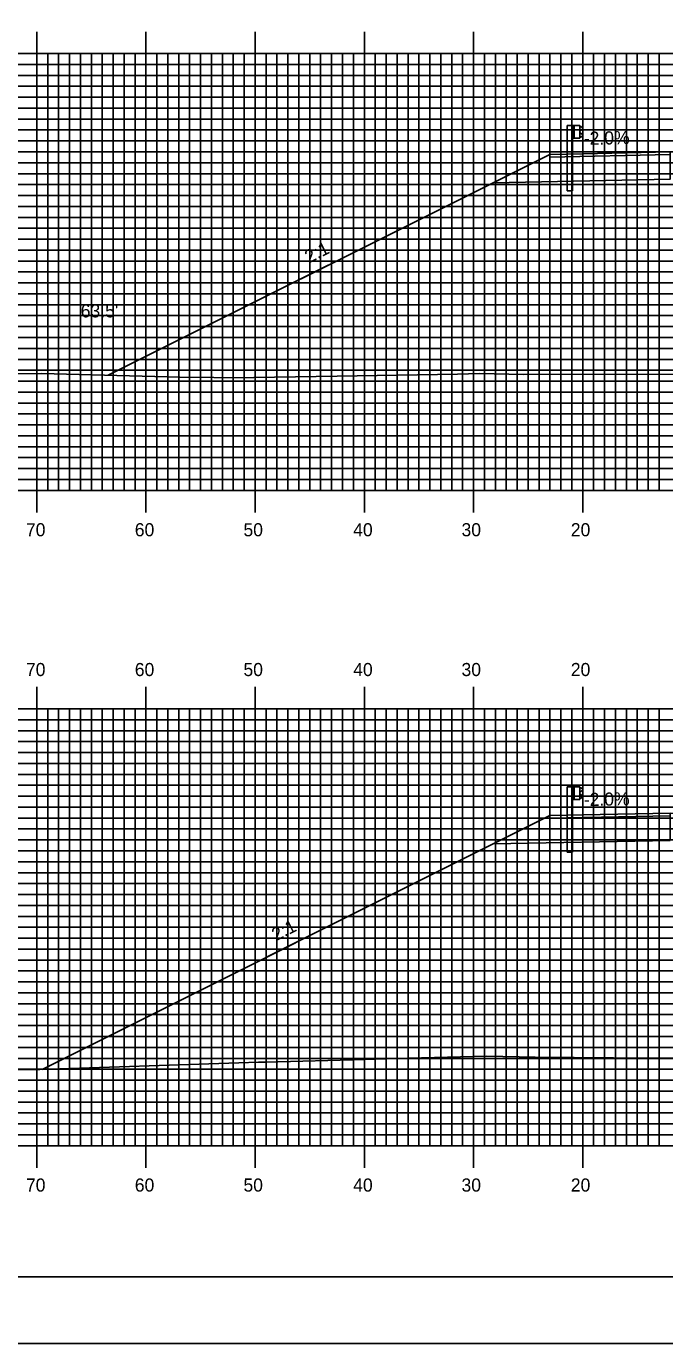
# Model space of a CAD drawing. Extents: x 1811374 to 1811717, y 442591 to 442811.
# Drawn here: x 1811468.4 to 1811526.9, y 442590.5 to 442711.2 of the extents above; entities that cross this region are included whole.
import ezdxf

# ---------------------------------------------------------------- set-up
doc = ezdxf.new("R2010")
doc.units = 0
for name, color, linetype in [('ANNOTATION', 7, 'Continuous'), ('BORDER', 7, 'Continuous'), ('D_Guardrail_Beam_Lt', 7, 'Continuous'), ('D_Roadway_Centerline', 7, 'Continuous'), ('D_Roadway_Edge_Shoulder', 7, 'Continuous'), ('D_Roadway_SlopeLines', 7, 'Continuous'), ('D_Roadway_SubGrade', 7, 'Continuous'), ('D_Text_Standard', 7, 'Continuous'), ('H_V ANNOTATION', 7, 'Continuous'), ('MAJOR', 7, 'Continuous'), ('MINOR', 7, 'Continuous'), ('PLOT BOUNDARY', 7, 'Continuous'), ('S_Roadway_Centerline', 7, 'Continuous')]:
    doc.layers.add(name, color=color, linetype=linetype)

msp = doc.modelspace()

# ---------------------------------------------------------------- linework, layer by layer
at = {"layer": 'BORDER'}
msp.add_lwpolyline([(1811389.8, 442596.67), (1811709.8, 442596.67), (1811709.8, 442806.67), (1811389.8, 442806.67)], close=True, dxfattribs=at)
at = {"layer": 'D_Guardrail_Beam_Lt'}
for p, q in [((1811517.97, 442702.09), (1811517.97, 442696.09)), ((1811518.44, 442702.09), (1811517.97, 442702.09)), ((1811519.13, 442702.09), (1811518.44, 442702.09)), ((1811518.44, 442702.09), (1811518.44, 442700.92)), ((1811518.51, 442702.09), (1811518.51, 442700.92)), ((1811518.61, 442702.09), (1811518.61, 442700.92)), ((1811519.13, 442700.92), (1811519.13, 442702.09)), ((1811519.13, 442702), (1811519.21, 442701.99)), ((1811519.22, 442701.98), (1811519.37, 442701.88)), ((1811518.44, 442700.92), (1811519.13, 442700.92)), ((1811518.47, 442696.09), (1811518.47, 442700.92)), ((1811519.21, 442701.02), (1811519.13, 442701)), ((1811519.14, 442701.54), (1811519.14, 442701.47)), ((1811519.37, 442701.74), (1811519.17, 442701.6)), ((1811519.17, 442701.4), (1811519.37, 442701.27)), ((1811519.37, 442701.12), (1811519.22, 442701.02)), ((1811518.47, 442696.09), (1811517.97, 442696.09)), ((1811517.97, 442641.54), (1811517.97, 442635.54)), ((1811518.44, 442641.54), (1811517.97, 442641.54)), ((1811519.13, 442641.54), (1811518.44, 442641.54)), ((1811518.44, 442641.54), (1811518.44, 442640.38)), ((1811518.44, 442640.38), (1811519.13, 442640.38)), ((1811518.47, 442635.54), (1811518.47, 442640.38)), ((1811518.51, 442641.54), (1811518.51, 442640.38)), ((1811518.61, 442641.54), (1811518.61, 442640.38)), ((1811519.13, 442640.38), (1811519.13, 442641.54)), ((1811519.13, 442641.46), (1811519.21, 442641.45)), ((1811519.21, 442640.48), (1811519.13, 442640.46)), ((1811519.14, 442641), (1811519.14, 442640.93)), ((1811519.37, 442641.2), (1811519.17, 442641.06)), ((1811519.17, 442640.86), (1811519.37, 442640.73)), ((1811519.22, 442641.44), (1811519.37, 442641.34)), ((1811519.37, 442640.58), (1811519.22, 442640.48)), ((1811518.47, 442635.54), (1811517.97, 442635.54))]:
    msp.add_line(p, q, dxfattribs=at)
for centre, major_axis, start_param, end_param in [((1811519.2, 442701.95), (0.0417, 0), 0.959931, 1.376053), ((1811519.32, 442701.81), (0.0877, 0), 5.323254, 7.243116), ((1811519.22, 442701.54), (-0.0789, 0), 5.323254, 6.283185), ((1811519.22, 442701.47), (-0.0789, 0), 6.283185, 7.243116), ((1811519.2, 442701.06), (0.0417, 0), 4.907132, 5.323254), ((1811519.32, 442701.19), (0.0877, 0), 5.323254, 7.243116), ((1811519.22, 442641), (-0.0789, 0), 5.323254, 6.283185), ((1811519.22, 442640.93), (-0.0789, 0), 6.283185, 7.243116), ((1811519.2, 442641.41), (0.0417, 0), 0.959931, 1.376053), ((1811519.2, 442640.52), (0.0417, 0), 4.907132, 5.323254), ((1811519.32, 442641.27), (0.0877, 0), 5.323254, 7.243116), ((1811519.32, 442640.65), (0.0877, 0), 5.323254, 7.243116)]:
    msp.add_ellipse(centre, major_axis=major_axis, ratio=0.995501, start_param=start_param, end_param=end_param, dxfattribs=at)
at = {"layer": 'D_Roadway_Centerline'}
for points in [[(1811475.94, 442679.21), (1811511.19, 442696.84), (1811516.4, 442699.44), (1811519.4, 442699.5), (1811527.4, 442699.66), (1811539.4, 442699.09), (1811551.4, 442698.51), (1811559.4, 442698.13), (1811562.4, 442697.98), (1811567.93, 442695.22), (1811602.42, 442677.97)], [(1811469.9, 442615.65), (1811511.19, 442636.3), (1811516.4, 442638.9), (1811519.4, 442638.96), (1811527.4, 442639.12), (1811539.4, 442638.54), (1811551.4, 442637.97), (1811559.4, 442637.58), (1811562.4, 442637.44), (1811567.93, 442634.68), (1811605.84, 442615.72)]]:
    msp.add_lwpolyline(points, dxfattribs=at)
at = {"layer": 'D_Roadway_Edge_Shoulder'}
for points in [[(1811527.4, 442699.66), (1811519.4, 442699.5), (1811519.4, 442699.5), (1811516.4, 442699.44), (1811516.4, 442699.19), (1811527.4, 442699.41)], [(1811527.4, 442639.12), (1811519.4, 442638.96), (1811519.4, 442638.96), (1811516.4, 442638.9), (1811516.4, 442638.65), (1811527.4, 442638.87)]]:
    msp.add_lwpolyline(points, close=True, dxfattribs=at)
at = {"layer": 'D_Roadway_SlopeLines'}
for points in [[(1811516.4, 442699.44), (1811475.94, 442679.21)], [(1811516.4, 442638.9), (1811469.9, 442615.65)]]:
    msp.add_lwpolyline(points, dxfattribs=at)
at = {"layer": 'D_Roadway_SubGrade'}
for points in [[(1811527.4, 442699), (1811527.4, 442699.41), (1811516.4, 442699.19), (1811516.4, 442699.44), (1811511.19, 442696.84), (1811527.4, 442697.16)], [(1811527.4, 442638.45), (1811527.4, 442638.87), (1811516.4, 442638.65), (1811516.4, 442638.9), (1811511.19, 442636.3), (1811527.4, 442636.62)]]:
    msp.add_lwpolyline(points, close=True, dxfattribs=at)
at = {"layer": 'MAJOR'}
for p, q in [((1811469.4, 442710.67), (1811469.4, 442708.67)), ((1811479.4, 442710.67), (1811479.4, 442708.67)), ((1811489.4, 442710.67), (1811489.4, 442708.67)), ((1811499.4, 442710.67), (1811499.4, 442708.67)), ((1811509.4, 442710.67), (1811509.4, 442708.67)), ((1811519.4, 442710.67), (1811519.4, 442708.67)), ((1811399.4, 442708.67), (1811679.4, 442708.67)), ((1811399.4, 442708.67), (1811679.4, 442708.67)), ((1811469.4, 442668.67), (1811469.4, 442708.67)), ((1811479.4, 442668.67), (1811479.4, 442708.67)), ((1811489.4, 442668.67), (1811489.4, 442708.67)), ((1811499.4, 442668.67), (1811499.4, 442708.67)), ((1811509.4, 442668.67), (1811509.4, 442708.67)), ((1811519.4, 442668.67), (1811519.4, 442708.67)), ((1811399.4, 442703.67), (1811679.4, 442703.67)), ((1811399.4, 442698.67), (1811679.4, 442698.67)), ((1811399.4, 442693.67), (1811679.4, 442693.67)), ((1811399.4, 442688.67), (1811679.4, 442688.67)), ((1811399.4, 442683.67), (1811679.4, 442683.67)), ((1811399.4, 442678.67), (1811679.4, 442678.67)), ((1811399.4, 442673.67), (1811679.4, 442673.67)), ((1811399.4, 442668.67), (1811679.4, 442668.67)), ((1811399.4, 442668.67), (1811679.4, 442668.67)), ((1811469.4, 442666.66), (1811469.4, 442668.67)), ((1811479.4, 442666.66), (1811479.4, 442668.67)), ((1811489.4, 442666.66), (1811489.4, 442668.67)), ((1811499.4, 442666.66), (1811499.4, 442668.67)), ((1811509.4, 442666.66), (1811509.4, 442668.67)), ((1811519.4, 442666.66), (1811519.4, 442668.67)), ((1811469.4, 442650.67), (1811469.4, 442648.67)), ((1811479.4, 442650.67), (1811479.4, 442648.67)), ((1811489.4, 442650.67), (1811489.4, 442648.67)), ((1811499.4, 442650.67), (1811499.4, 442648.67)), ((1811509.4, 442650.67), (1811509.4, 442648.67)), ((1811519.4, 442650.67), (1811519.4, 442648.67)), ((1811399.4, 442648.67), (1811679.4, 442648.67)), ((1811399.4, 442648.67), (1811679.4, 442648.67)), ((1811469.4, 442608.67), (1811469.4, 442648.67)), ((1811479.4, 442608.67), (1811479.4, 442648.67)), ((1811489.4, 442608.67), (1811489.4, 442648.67)), ((1811499.4, 442608.67), (1811499.4, 442648.67)), ((1811509.4, 442608.67), (1811509.4, 442648.67)), ((1811519.4, 442608.67), (1811519.4, 442648.67)), ((1811399.4, 442643.67), (1811679.4, 442643.67)), ((1811399.4, 442638.67), (1811679.4, 442638.67)), ((1811399.4, 442633.67), (1811679.4, 442633.67)), ((1811399.4, 442628.67), (1811679.4, 442628.67)), ((1811399.4, 442623.67), (1811679.4, 442623.67)), ((1811399.4, 442618.67), (1811679.4, 442618.67)), ((1811399.4, 442613.67), (1811679.4, 442613.67)), ((1811399.4, 442608.67), (1811679.4, 442608.67)), ((1811399.4, 442608.67), (1811679.4, 442608.67)), ((1811469.4, 442606.66), (1811469.4, 442608.67)), ((1811479.4, 442606.66), (1811479.4, 442608.67)), ((1811489.4, 442606.66), (1811489.4, 442608.67)), ((1811499.4, 442606.66), (1811499.4, 442608.67)), ((1811509.4, 442606.66), (1811509.4, 442608.67)), ((1811519.4, 442606.66), (1811519.4, 442608.67))]:
    msp.add_line(p, q, dxfattribs=at)
at = {"layer": 'MINOR'}
for p, q in [((1811470.4, 442668.67), (1811470.4, 442708.67)), ((1811471.4, 442668.67), (1811471.4, 442708.67)), ((1811472.4, 442668.67), (1811472.4, 442708.67)), ((1811473.4, 442668.67), (1811473.4, 442708.67)), ((1811474.4, 442668.67), (1811474.4, 442708.67)), ((1811475.4, 442668.67), (1811475.4, 442708.67)), ((1811476.4, 442668.67), (1811476.4, 442708.67)), ((1811477.4, 442668.67), (1811477.4, 442708.67)), ((1811478.4, 442668.67), (1811478.4, 442708.67)), ((1811480.4, 442668.67), (1811480.4, 442708.67)), ((1811481.4, 442668.67), (1811481.4, 442708.67)), ((1811482.4, 442668.67), (1811482.4, 442708.67)), ((1811483.4, 442668.67), (1811483.4, 442708.67)), ((1811484.4, 442668.67), (1811484.4, 442708.67)), ((1811485.4, 442668.67), (1811485.4, 442708.67)), ((1811486.4, 442668.67), (1811486.4, 442708.67)), ((1811487.4, 442668.67), (1811487.4, 442708.67)), ((1811488.4, 442668.67), (1811488.4, 442708.67)), ((1811490.4, 442668.67), (1811490.4, 442708.67)), ((1811491.4, 442668.67), (1811491.4, 442708.67)), ((1811492.4, 442668.67), (1811492.4, 442708.67)), ((1811493.4, 442668.67), (1811493.4, 442708.67)), ((1811494.4, 442668.67), (1811494.4, 442708.67)), ((1811495.4, 442668.67), (1811495.4, 442708.67)), ((1811496.4, 442668.67), (1811496.4, 442708.67)), ((1811497.4, 442668.67), (1811497.4, 442708.67)), ((1811498.4, 442668.67), (1811498.4, 442708.67)), ((1811500.4, 442668.67), (1811500.4, 442708.67)), ((1811501.4, 442668.67), (1811501.4, 442708.67)), ((1811502.4, 442668.67), (1811502.4, 442708.67)), ((1811503.4, 442668.67), (1811503.4, 442708.67)), ((1811504.4, 442668.67), (1811504.4, 442708.67)), ((1811505.4, 442668.67), (1811505.4, 442708.67)), ((1811506.4, 442668.67), (1811506.4, 442708.67)), ((1811507.4, 442668.67), (1811507.4, 442708.67)), ((1811508.4, 442668.67), (1811508.4, 442708.67)), ((1811510.4, 442668.67), (1811510.4, 442708.67)), ((1811511.4, 442668.67), (1811511.4, 442708.67)), ((1811512.4, 442668.67), (1811512.4, 442708.67)), ((1811513.4, 442668.67), (1811513.4, 442708.67)), ((1811514.4, 442668.67), (1811514.4, 442708.67)), ((1811515.4, 442668.67), (1811515.4, 442708.67)), ((1811516.4, 442668.67), (1811516.4, 442708.67)), ((1811517.4, 442668.67), (1811517.4, 442708.67)), ((1811518.4, 442668.67), (1811518.4, 442708.67)), ((1811520.4, 442668.67), (1811520.4, 442708.67)), ((1811521.4, 442668.67), (1811521.4, 442708.67)), ((1811522.4, 442668.67), (1811522.4, 442708.67)), ((1811523.4, 442668.67), (1811523.4, 442708.67)), ((1811524.4, 442668.67), (1811524.4, 442708.67)), ((1811525.4, 442668.67), (1811525.4, 442708.67)), ((1811526.4, 442668.67), (1811526.4, 442708.67)), ((1811399.4, 442707.67), (1811679.4, 442707.67)), ((1811399.4, 442706.67), (1811679.4, 442706.67)), ((1811399.4, 442705.67), (1811679.4, 442705.67)), ((1811399.4, 442704.67), (1811679.4, 442704.67)), ((1811399.4, 442702.67), (1811679.4, 442702.67)), ((1811399.4, 442701.67), (1811679.4, 442701.67)), ((1811399.4, 442700.67), (1811679.4, 442700.67)), ((1811399.4, 442699.67), (1811679.4, 442699.67)), ((1811399.4, 442697.67), (1811679.4, 442697.67)), ((1811399.4, 442696.67), (1811679.4, 442696.67)), ((1811399.4, 442695.67), (1811679.4, 442695.67)), ((1811399.4, 442694.67), (1811679.4, 442694.67)), ((1811399.4, 442692.67), (1811679.4, 442692.67)), ((1811399.4, 442691.67), (1811679.4, 442691.67)), ((1811399.4, 442690.67), (1811679.4, 442690.67)), ((1811399.4, 442689.67), (1811679.4, 442689.67)), ((1811399.4, 442687.67), (1811679.4, 442687.67)), ((1811399.4, 442686.67), (1811679.4, 442686.67)), ((1811399.4, 442685.67), (1811679.4, 442685.67)), ((1811399.4, 442684.67), (1811679.4, 442684.67)), ((1811399.4, 442682.67), (1811679.4, 442682.67)), ((1811399.4, 442681.67), (1811679.4, 442681.67)), ((1811399.4, 442680.67), (1811679.4, 442680.67)), ((1811399.4, 442679.67), (1811679.4, 442679.67)), ((1811399.4, 442677.67), (1811679.4, 442677.67)), ((1811399.4, 442676.67), (1811679.4, 442676.67)), ((1811399.4, 442675.67), (1811679.4, 442675.67)), ((1811399.4, 442674.67), (1811679.4, 442674.67)), ((1811399.4, 442672.67), (1811679.4, 442672.67)), ((1811399.4, 442671.67), (1811679.4, 442671.67)), ((1811399.4, 442670.67), (1811679.4, 442670.67)), ((1811399.4, 442669.67), (1811679.4, 442669.67)), ((1811399.4, 442647.67), (1811679.4, 442647.67)), ((1811470.4, 442608.67), (1811470.4, 442648.67)), ((1811471.4, 442608.67), (1811471.4, 442648.67)), ((1811472.4, 442608.67), (1811472.4, 442648.67)), ((1811473.4, 442608.67), (1811473.4, 442648.67)), ((1811474.4, 442608.67), (1811474.4, 442648.67)), ((1811475.4, 442608.67), (1811475.4, 442648.67)), ((1811476.4, 442608.67), (1811476.4, 442648.67)), ((1811477.4, 442608.67), (1811477.4, 442648.67)), ((1811478.4, 442608.67), (1811478.4, 442648.67)), ((1811480.4, 442608.67), (1811480.4, 442648.67)), ((1811481.4, 442608.67), (1811481.4, 442648.67)), ((1811482.4, 442608.67), (1811482.4, 442648.67)), ((1811483.4, 442608.67), (1811483.4, 442648.67)), ((1811484.4, 442608.67), (1811484.4, 442648.67)), ((1811485.4, 442608.67), (1811485.4, 442648.67)), ((1811486.4, 442608.67), (1811486.4, 442648.67)), ((1811487.4, 442608.67), (1811487.4, 442648.67)), ((1811488.4, 442608.67), (1811488.4, 442648.67)), ((1811490.4, 442608.67), (1811490.4, 442648.67)), ((1811491.4, 442608.67), (1811491.4, 442648.67)), ((1811492.4, 442608.67), (1811492.4, 442648.67)), ((1811493.4, 442608.67), (1811493.4, 442648.67)), ((1811494.4, 442608.67), (1811494.4, 442648.67)), ((1811495.4, 442608.67), (1811495.4, 442648.67)), ((1811496.4, 442608.67), (1811496.4, 442648.67)), ((1811497.4, 442608.67), (1811497.4, 442648.67)), ((1811498.4, 442608.67), (1811498.4, 442648.67)), ((1811500.4, 442608.67), (1811500.4, 442648.67)), ((1811501.4, 442608.67), (1811501.4, 442648.67)), ((1811502.4, 442608.67), (1811502.4, 442648.67)), ((1811503.4, 442608.67), (1811503.4, 442648.67)), ((1811504.4, 442608.67), (1811504.4, 442648.67)), ((1811505.4, 442608.67), (1811505.4, 442648.67)), ((1811506.4, 442608.67), (1811506.4, 442648.67)), ((1811507.4, 442608.67), (1811507.4, 442648.67)), ((1811508.4, 442608.67), (1811508.4, 442648.67)), ((1811510.4, 442608.67), (1811510.4, 442648.67)), ((1811511.4, 442608.67), (1811511.4, 442648.67)), ((1811512.4, 442608.67), (1811512.4, 442648.67)), ((1811513.4, 442608.67), (1811513.4, 442648.67)), ((1811514.4, 442608.67), (1811514.4, 442648.67)), ((1811515.4, 442608.67), (1811515.4, 442648.67)), ((1811516.4, 442608.67), (1811516.4, 442648.67)), ((1811517.4, 442608.67), (1811517.4, 442648.67)), ((1811518.4, 442608.67), (1811518.4, 442648.67)), ((1811520.4, 442608.67), (1811520.4, 442648.67)), ((1811521.4, 442608.67), (1811521.4, 442648.67)), ((1811522.4, 442608.67), (1811522.4, 442648.67)), ((1811523.4, 442608.67), (1811523.4, 442648.67)), ((1811524.4, 442608.67), (1811524.4, 442648.67)), ((1811525.4, 442608.67), (1811525.4, 442648.67)), ((1811526.4, 442608.67), (1811526.4, 442648.67)), ((1811399.4, 442646.67), (1811679.4, 442646.67)), ((1811399.4, 442645.67), (1811679.4, 442645.67)), ((1811399.4, 442644.67), (1811679.4, 442644.67)), ((1811399.4, 442642.67), (1811679.4, 442642.67)), ((1811399.4, 442641.67), (1811679.4, 442641.67)), ((1811399.4, 442640.67), (1811679.4, 442640.67)), ((1811399.4, 442639.67), (1811679.4, 442639.67)), ((1811399.4, 442637.67), (1811679.4, 442637.67)), ((1811399.4, 442636.67), (1811679.4, 442636.67)), ((1811399.4, 442635.67), (1811679.4, 442635.67)), ((1811399.4, 442634.67), (1811679.4, 442634.67)), ((1811399.4, 442632.67), (1811679.4, 442632.67)), ((1811399.4, 442631.67), (1811679.4, 442631.67)), ((1811399.4, 442630.67), (1811679.4, 442630.67)), ((1811399.4, 442629.67), (1811679.4, 442629.67)), ((1811399.4, 442627.67), (1811679.4, 442627.67)), ((1811399.4, 442626.67), (1811679.4, 442626.67)), ((1811399.4, 442625.67), (1811679.4, 442625.67)), ((1811399.4, 442624.67), (1811679.4, 442624.67)), ((1811399.4, 442622.67), (1811679.4, 442622.67)), ((1811399.4, 442621.67), (1811679.4, 442621.67)), ((1811399.4, 442620.67), (1811679.4, 442620.67)), ((1811399.4, 442619.67), (1811679.4, 442619.67)), ((1811399.4, 442617.67), (1811679.4, 442617.67)), ((1811399.4, 442616.67), (1811679.4, 442616.67)), ((1811399.4, 442615.67), (1811679.4, 442615.67)), ((1811399.4, 442614.67), (1811679.4, 442614.67)), ((1811399.4, 442612.67), (1811679.4, 442612.67)), ((1811399.4, 442611.67), (1811679.4, 442611.67)), ((1811399.4, 442610.67), (1811679.4, 442610.67)), ((1811399.4, 442609.67), (1811679.4, 442609.67))]:
    msp.add_line(p, q, dxfattribs=at)
at = {"layer": 'PLOT BOUNDARY'}
msp.add_lwpolyline([(1811373.62, 442590.55), (1811713.62, 442590.55), (1811713.62, 442810.55), (1811373.62, 442810.55)], close=True, dxfattribs=at)
at = {"layer": 'S_Roadway_Centerline'}
for points in [[(1811451.55, 442679.34), (1811469.83, 442679.36), (1811482.49, 442679.05), (1811485.62, 442679), (1811487.37, 442678.98), (1811496.91, 442679.12), (1811507.94, 442679.32), (1811509.95, 442679.36), (1811513.99, 442679.28), (1811534.49, 442679.3), (1811545.39, 442679.21), (1811546.89, 442679.18), (1811558.7, 442679.05), (1811565.95, 442678.73), (1811570.24, 442678.49), (1811581.07, 442678.29), (1811583.44, 442678.27), (1811584.52, 442678.3), (1811590.01, 442678.19), (1811602.72, 442677.97)], [(1811466.87, 442615.61), (1811469.67, 442615.64), (1811487.91, 442616.26), (1811489.7, 442616.33), (1811489.97, 442616.33), (1811490.34, 442616.33), (1811499.49, 442616.56), (1811502.21, 442616.65), (1811510.63, 442616.87), (1811515.03, 442616.78), (1811522.23, 442616.71), (1811535.32, 442616.69), (1811546.76, 442616.67), (1811554.79, 442616.36), (1811563.75, 442616.37), (1811574.07, 442616.6), (1811581.46, 442616.35), (1811593.48, 442615.24), (1811595.85, 442615.25), (1811605.4, 442615.73)]]:
    msp.add_lwpolyline(points, dxfattribs=at)

# ---------------------------------------------------------------- texts
at = {"layer": 'ANNOTATION'}
for s, rotation, p in [('-2.0%', 1.1458, (1811519.51, 442700.3)), ('2:1', 26.5651, (1811494.32, 442689.44)), ('-2.0%', 1.1458, (1811519.51, 442639.76)), ('2:1', 26.5651, (1811491.3, 442627.38))]:
    msp.add_text(s, height=1.2, rotation=rotation, dxfattribs=at).set_placement(p)
at = {"layer": 'D_Text_Standard'}
msp.add_text("63.5'", height=1.2, dxfattribs=at).set_placement((1811473.43, 442684.51))
at = {"layer": 'H_V ANNOTATION'}
for s, p in [('70', (1811468.41, 442664.47)), ('60', (1811478.38, 442664.47)), ('50', (1811488.33, 442664.47)), ('40', (1811498.38, 442664.47)), ('30', (1811508.3, 442664.47)), ('20', (1811518.31, 442664.47)), ('70', (1811468.41, 442651.67)), ('60', (1811478.38, 442651.67)), ('50', (1811488.33, 442651.67)), ('40', (1811498.38, 442651.67)), ('30', (1811508.3, 442651.67)), ('20', (1811518.31, 442651.67)), ('70', (1811468.41, 442604.47)), ('60', (1811478.38, 442604.47)), ('50', (1811488.33, 442604.47)), ('40', (1811498.38, 442604.47)), ('30', (1811508.3, 442604.47)), ('20', (1811518.31, 442604.47))]:
    msp.add_text(s, height=1.2, dxfattribs=at).set_placement(p)

doc.saveas('drawing.dxf')
